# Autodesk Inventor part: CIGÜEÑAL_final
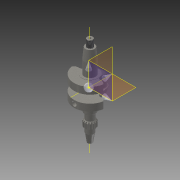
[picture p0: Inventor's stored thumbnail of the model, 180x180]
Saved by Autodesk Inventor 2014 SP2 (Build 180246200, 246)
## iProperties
Created: 2015-07
Part Number: CIGÜEÑAL_final
Material: Acero, fundido
Document SubType Name: Modeling
Designer: Jaime
Density: 7.76737 g/cm^3
Appearance: Acero - Fundido
Mass: 5489.2 g
Surface Area: 835.449 cm^2
Volume: 706.7 cm^3
Author: Jaime
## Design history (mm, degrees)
sketch "Boceto1"
  geometry: C1 r 20 at (0, 37.5); 1 further point
  constraints: 1 centre point
  dimensions: "d0" = 37.5 distance of point (0, 0) C1.centre (= Muñequilla); "d1" = 40 diameter of C1
extrude "Extrusión1" new body sketch "Boceto1" stored distance "d2" = 30; taper "d3" = 0 deg
sketch "Boceto2"
  geometry: L1 (-22.577, 4.389)-(-29.153, -29.442); L2 (22.577, 4.389)-(29.153, -29.442); L3 (0, 30)-(0, -77.072); L4 (39.656, -38.1)-(43.176, -38.1); L5 (-39.656, -38.1)-(-43.176, -38.1); C1 r 20 at (0, 0) reference; A1 r 23 centre (0, 0) between (22.577, 4.389) and (-22.577, 4.389); A2 r 10.7 centre (-39.656, -27.4) between (-39.656, -38.1) and (-29.153, -29.442); A3 r 60.5 centre (0, -37.5) between (-59.8, -46.677) and (59.8, -46.677); A4 r 10.7 centre (39.656, -27.4) between (29.153, -29.442) and (39.656, -38.1); A5 r 20.399 centre (43.176, -58.499) between (59.8, -46.677) and (43.176, -38.1); A6 r 20.399 centre (-43.176, -58.499) between (-43.176, -38.1) and (-59.8, -46.677); 1 further point
  constraints: 12 point on circle, 10 end point, 8 tangent, 6 centre point, 3 symmetric about line, 2 vertical alignment, 1 coincident, 1 perpendicular, 1 vertical, 1 other
  dimensions: "d4" = 23 radius of A1; "d5" = 60.5 radius of A3; "d6" = 121 dimension on A3 A1; "d10" = 22 deg angle of L2 L1; "d14" = 43.17607 distance from line of L3 A5.centre; "d15" = 0.6 distance from line of A3.centre L4; "d18" = 119.6 distance of A3.end A3.start; "d20" = 10.69951 radius of A2
extrude "Extrusión2" join sketch "Boceto2" distance "d16" = 26; taper "d17" = 0 deg
mirror "Simetría1"
fillet "Empalme1" dims "d21" = 3
sketch "Boceto4"
  geometry: L1 (60.5, 15)-(60.5, 41) reference; L2 (41.889, 41)-(8.058, 41) reference; L3 (2.64, 70.063)-(60.5, 70.063); L4 (60.5, 70.063)-(60.5, 15.869); L5 (2.64, 70.063)-(2.64, 53.162); L6 (-85.328, 0)-(88.469, 0) reference; A1 r 98.375 centre (-18.357, -42.946) between (60.5, 15.869) and (2.64, 53.162); 3 further points
  constraints: 6 end point, 2 parallel, 2 point on circle, 1 centre point, 1 midpoint, 1 point on line, 1 vertical alignment
revolve "Revolución2" sketch "Boceto4" stored, may be unused: angle "d25" = 90 deg
fillet "Empalme2" dims "d26" = 2
sketch "Boceto5"
  geometry: C1 r 30 at (0, -37.5); A1 r 60.5 centre (0, -37.5) between (-59.8, -46.677) and (59.8, -46.677) reference
  constraints: 1 centre point, 1 coincident
  dimensions: "d27" = 60 diameter of C1
extrude "Extrusión3" join sketch "Boceto5" distance "d28" = 1; taper "d29" = 0 deg
mirror "Simetría2"
sketch "Boceto6"
  geometry: C1 r 30 at (0, 0) reference; C2 r 21 at (0, 0)
  constraints: 1 centre point, 1 coincident
  dimensions: "d30" = 42 diameter of C2
extrude "Extrusión4" join sketch "Boceto6" distance "d31" = 89.6; taper "d32" = 0 deg
sketch "Boceto7"
  geometry: L1 (17, 131.6)-(21, 91.6); L2 (21, 91.6)-(21, 131.6); L3 (21, 131.6)-(17, 131.6); L4 (21, 131.6)-(-21, 131.6) reference; L5 (21, 42)-(21, 131.6) reference; L6 (0, -77.507)-(0, 166.801) reference; 1 further point
  constraints: 6 end point, 1 perpendicular, 1 vertical
  dimensions: "d33" = 0 distance between parallel lines of L4 L3; "d34" = 0 distance between parallel lines of L5 L2; "d35" = 17 horizontal distance of point (0, 0) L1.start; "d36" = 40 distance of L1.end L2.end
revolve "Revolución3" sketch "Boceto7" stored, may be unused: angle "d37" = 90 deg
sketch "Boceto8"
  geometry: C1 r 17 at (0, 0) reference; C2 r 11 at (0, 0)
  constraints: 1 centre point, 1 coincident
  dimensions: "d38" = 22 diameter of C2
extrude "Extrusión5" join sketch "Boceto8" distance "d39" = 27.9; taper "d40" = 0 deg
feature "Rosca2" dims "d43" = 10, "d44" = 0
chamfer "Chaflán1" distance "d45" = 1; stored, may be unused: second distance "d46" = 2, angle "d47" = 45 deg
hole "Hole1" diameter "d50" = 8; stored, may be unused: countersink angle "d54" = 90 deg, drill point angle "d56" = 118 deg; dims "d48" = 10, "d49" = 10, "d51" = 6, "d52" = 4, "d53" = 2, "d55" = 8
node "Plano de trabajo1"
sketch "Boceto9"
  geometry: L1 (0, 125.6)-(0, 98.6); L2 (-4, 125.6)-(-4, 98.6); L3 (4, 98.6)-(4, 125.6); L4 (17, 131.6)-(-17, 131.6) reference; A1 r 4 centre (0, 125.6) between (4, 125.6) and (-4, 125.6); A2 r 4 centre (0, 98.6) between (-4, 98.6) and (4, 98.6); 2 further points
  constraints: 8 end point, 4 point on circle, 4 tangent, 2 centre point, 1 midpoint, 1 parallel, 1 vertical
  dimensions: "d58" = 27 distance of L1.start L1.end; "d59" = 8 diameter of A2; "d60" = 0 distance from line of point (0, 0) L1; "d61" = 6 distance from line of L4 L1.start
extrude "Extrusión6" cut sketch "Boceto9" distance "d62" = 16.9; taper "d63" = 0 deg
sketch "Boceto10"
  geometry: C1 r 30 at (0, 0) reference; C2 r 21 at (0, 0)
  constraints: 1 centre point, 1 coincident
  dimensions: "d64" = 42 diameter of C2
extrude "Extrusión7" join sketch "Boceto10" distance "d65" = 40; taper "d66" = 0 deg
sketch "Boceto11"
  geometry: C1 r 21 at (0, 0) reference; C2 r 15.4 at (0, 0)
  constraints: 1 centre point, 1 coincident
  dimensions: "d67" = 30.8 diameter of C2
extrude "Extrusión8" join sketch "Boceto11" distance "d68" = 24; taper "d69" = 0 deg
sketch "Boceto13"
  geometry: L1 (16.967, -2.419)-(17.015, -2.655); L2 (17.015, -2.655)-(17.085, -2.754); L3 (17.085, -2.754)-(17.159, -2.829); L4 (17.159, -2.829)-(17.235, -2.891); L5 (17.235, -2.891)-(17.392, -2.989); L6 (17.392, -2.989)-(17.552, -3.065); L7 (17.552, -3.065)-(17.88, -3.182); L8 (17.88, -3.182)-(18.203, -3.323); L9 (18.203, -3.323)-(18.519, -3.491); L10 (18.519, -3.491)-(18.831, -3.682); L11 (18.831, -3.682)-(19.137, -3.893); L12 (19.137, -3.893)-(19.439, -4.122); L13 (19.439, -4.122)-(19.734, -4.369); L14 (19.734, -4.369)-(20.025, -4.632); L15 (20.025, -4.632)-(19.16, -7.331); L16 (19.16, -7.331)-(18.771, -7.376); L17 (18.771, -7.376)-(18.387, -7.405); L18 (18.387, -7.405)-(18.009, -7.417); L19 (18.009, -7.417)-(17.637, -7.41); L20 (17.637, -7.41)-(17.272, -7.385); L21 (17.272, -7.385)-(16.917, -7.337); L22 (16.917, -7.337)-(16.572, -7.264); L23 (16.572, -7.264)-(16.237, -7.17); L24 (16.237, -7.17)-(16.063, -7.138); L25 (16.063, -7.138)-(15.878, -7.127); L26 (15.878, -7.127)-(15.78, -7.133); L27 (15.78, -7.133)-(15.677, -7.151); L28 (15.677, -7.151)-(15.562, -7.191); L29 (15.562, -7.191)-(15.386, -7.355); L30 (15.386, -7.355)-(14.397, -9.085); L31 (14.397, -9.085)-(14.345, -9.32); L32 (14.345, -9.32)-(14.368, -9.439); L33 (14.368, -9.439)-(14.405, -9.537); L34 (14.405, -9.537)-(14.45, -9.625); L35 (14.45, -9.625)-(14.553, -9.778); L36 (14.553, -9.778)-(14.669, -9.913); L37 (14.669, -9.913)-(14.92, -10.153); L38 (14.92, -10.153)-(15.158, -10.413); L39 (15.158, -10.413)-(15.379, -10.695); L40 (15.379, -10.695)-(15.586, -10.996); L41 (15.586, -10.996)-(15.78, -11.314); L42 (15.78, -11.314)-(15.962, -11.646); L43 (15.962, -11.646)-(16.132, -11.991); L44 (16.132, -11.991)-(16.29, -12.35); L45 (16.29, -12.35)-(14.403, -14.464); L46 (14.403, -14.464)-(14.029, -14.347); L47 (14.029, -14.347)-(13.666, -14.217); L48 (13.666, -14.217)-(13.316, -14.074); L49 (13.316, -14.074)-(12.979, -13.917); L50 (12.979, -13.917)-(12.656, -13.745); L51 (12.656, -13.745)-(12.35, -13.558); L52 (12.35, -13.558)-(12.066, -13.351); L53 (12.066, -13.351)-(11.798, -13.128); L54 (11.798, -13.128)-(11.651, -13.028); L55 (11.651, -13.028)-(11.487, -12.943); L56 (11.487, -12.943)-(11.396, -12.909); L57 (11.396, -12.909)-(11.294, -12.883); L58 (11.294, -12.883)-(11.173, -12.873); L59 (11.173, -12.873)-(10.945, -12.951); L60 (10.945, -12.951)-(9.338, -14.129); L61 (9.338, -14.129)-(9.195, -14.323); L62 (9.195, -14.323)-(9.168, -14.441); L63 (9.168, -14.441)-(9.162, -14.546); L64 (9.162, -14.546)-(9.167, -14.644)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
  constraints: 952 end point, 26 parallel, 13 perpendicular, 4 point on line
extrude "Extrusión9" join sketch "Boceto13" distance "d70" = 26; taper "d71" = 0 deg
sketch "Boceto14"
  geometry: C1 r 15 at (0, 0); 1 further point
  constraints: 1 centre point, 1 coincident
  dimensions: "d72" = 30 diameter of C1
extrude "Extrusión10" join sketch "Boceto14" distance "d73" = 18; taper "d74" = 0 deg
sketch "Boceto15"
  geometry: L1 (-15, -150)-(15, -150) reference; L2 (8.83, -184)-(0, -184); L3 (0, -184)-(0, -150); L4 (0, -253.12)-(0, 228.62) reference; L5 (8.83, -184)-(13.521, -152.001); L6 (15, -132)-(15, -150) reference; A1 r 2 centre (15.5, -152.291) between (14.7, -150.458) and (13.521, -152.001); A2 r 0.5 centre (14.5, -150) between (14.7, -150.458) and (15, -150); 1 further point
  constraints: 6 end point, 4 point on circle, 3 tangent, 2 centre point, 1 midpoint, 1 parallel
  dimensions: "d75" = 34 distance between parallel lines of L2 L1; "d76" = 15 distance from line of L3 L1.end; "d77" = 8.83 distance of L2.start L2.end; "d84" = 0.5 radius of A2; "d85" = 2 radius of A1; "d86" = 0.5 distance from line of A1.centre L6
revolve "Revolución4" sketch "Boceto15" stored, may be unused: angle "d78" = 90 deg
sketch "Boceto16"
  geometry: L1 (0, -157)-(0, -177); L2 (-3, -157)-(-3, -177); L3 (3, -177)-(3, -157); L4 (-8.83, -184)-(8.83, -184) reference; A1 r 3 centre (0, -157) between (3, -157) and (-3, -157); A2 r 3 centre (0, -177) between (-3, -177) and (3, -177); 2 further points
  constraints: 8 end point, 4 point on circle, 4 tangent, 2 centre point, 1 midpoint, 1 parallel, 1 vertical, 1 vertical alignment
  dimensions: "d79" = 20 distance of L1.start L1.end; "d80" = 6 diameter of A2; "d81" = 27 distance from line of L4 L1.start
extrude "Extrusión11" cut sketch "Boceto16" distance "d82" = 23; taper "d83" = 0 deg
node "Punto de trabajo1"
hole "Hole2" diameter "d89" = 8.4; stored, may be unused: countersink angle "d93" = 90 deg, drill point angle "d95" = 118 deg; dims "d87" = 10, "d88" = 10, "d90" = 6, "d91" = 4, "d92" = 2, "d94" = 32.8
chamfer "Chaflán2" distance "d96" = 2; stored, may be unused: second distance "d97" = 2, angle "d98" = 45 deg
node "Punto de trabajo2"
node "Plano de trabajo3"
sketch "Boceto18"
  geometry: L1 (59.8, -30)-(-59.8, -30) reference; L2 (59.8, -56)-(-59.8, -56) reference; C1 r 8.68 at (0, -43); 1 further point
  constraints: 1 centre point
  dimensions: "d102" = 17.36 diameter of C1; "d103" = 13 distance from line of C1.centre L1
hole "Hole3" sketch "Boceto18" at (0, -43) diameter "d104" = 17.36; stored, may be unused: countersink angle "d108" = 90 deg, drill point angle "d110" = 118 deg; dims "d105" = 6, "d106" = 4, "d107" = 2, "d109" = 11.6
fillet "Empalme3" dims "d111" = 3
sketch "Boceto19"
  geometry: L1 (15.4, -85)-(15.4, -106) reference; L2 (15, -132)-(15, -150) reference; L3 (15.639, -106.28)-(21.9, -113.632); L4 (21.9, -113.632)-(21.9, -129.094); L5 (21.9, -129.094)-(16.224, -131.485); L6 (15, -133.328)-(15, -138.218); L7 (29.46, -138.218)-(29.46, -85); L8 (29.46, -85)-(15.4, -85); L9 (15.4, -85)-(15.4, -105.632); L10 (29.46, -138.218)-(15, -138.218); L11 (0, -253.12)-(0, 228.62) reference; A1 r 1 centre (16.4, -105.632) between (15.4, -105.632) and (15.639, -106.28); A2 r 2 centre (17, -133.328) between (16.224, -131.485) and (15, -133.328); 1 further point
  constraints: 16 end point, 5 point on line, 4 point on circle, 4 tangent, 2 centre point, 2 perpendicular, 1 collinear, 1 parallel
  dimensions: "d112" = 1 radius of A1; "d113" = 2 radius of A2; "d114" = 6.5 distance between parallel lines of L1 L4; "d115" = 8 vertical distance of L3.end L9.end
revolve "Revolución5" sketch "Boceto19" stored, may be unused: angle "d116" = 90 deg
node "Sólido1"
other parameters: "Muñequilla" = 37.5 [user parameter; used in 1 equation term], "d57" = 30.5
